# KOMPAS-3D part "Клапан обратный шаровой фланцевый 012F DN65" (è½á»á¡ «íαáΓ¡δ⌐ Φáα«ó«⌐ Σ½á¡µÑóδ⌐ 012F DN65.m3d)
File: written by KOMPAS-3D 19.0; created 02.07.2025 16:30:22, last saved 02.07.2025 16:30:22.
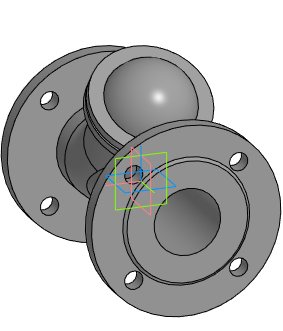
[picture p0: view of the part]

Document properties: Полное имя файла: E:\Dendor Работа Сачек\3D для проектировщиков\5.3 Тип 012F, 012F.Z Клапан обратный шаровой фланцевый\stp_Клапан обратный шаровой фланцевый 012F\Клапан обратный шаровой фланцевый 012F DN65.m3d

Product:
- Part/product: Клапан обратный шаровой фланцевый 012F DN65

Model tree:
1. Операция без истории:1  (labels: Клапан обратный шаровой фланцевый 012F DN65)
